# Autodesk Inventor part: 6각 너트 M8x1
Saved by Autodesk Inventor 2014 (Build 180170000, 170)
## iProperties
Created: 2025-10
Part Number: 6각 너트 M8x1
Material: 일반
Document SubType Name: Modeling
Designer: dg
Density: 1 g/cm^3
Appearance: 기본값
Author: dg
Author: jhkim
Description: 6각 너트 및 6각 가는 너트
Creation Date: 2025-10-01
Sending System: Autodesk Inventor 2026
Preprocessor: ST-DEVELOPER v20.1
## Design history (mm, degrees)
node "6각 너트 M8x11"
body "Solid1"
node "기준1"
